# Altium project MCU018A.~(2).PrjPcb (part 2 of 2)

## Sheet MCU018A_Main.SchDoc
size 558 x 431 mm; Date: Not shown in title block; ApprovedBy: Not shown in title block; CheckedBy: Not shown in title block; Author: Not shown in title block; CompanyName: Not shown in title block; Engineer: Eddie LaCost; Organization: Not shown in title block; Address1: Not shown in title block; Address2: Not shown in title block; Address3: Not shown in title block; Address4: Not shown in title block; DocumentNumber: 2; Revision: Use project parameter SCH_Rev; SheetNumber: 2; SheetTotal: 6; PageSetup: Record=PageOptions¦CenterHorizontal=True¦CenterVertical=True¦PrintScale=1.00¦XCorrection=1.00¦YCorrection=1.00¦PrintKind=0¦BorderSize=5000000¦LeftOffset=0¦BottomOffset=0¦Orientation=2¦PaperLength=1000¦PaperWidth=1000¦Scale=100¦PaperSource=15¦PrintQuality=600¦MediaType=1¦DitherType=10¦PaperKind=Letter¦PrintScaleMode=1
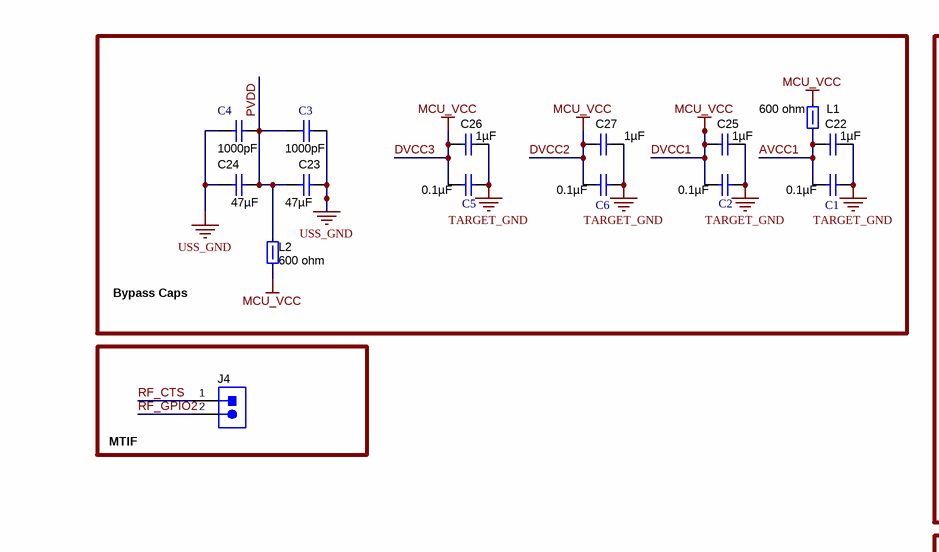
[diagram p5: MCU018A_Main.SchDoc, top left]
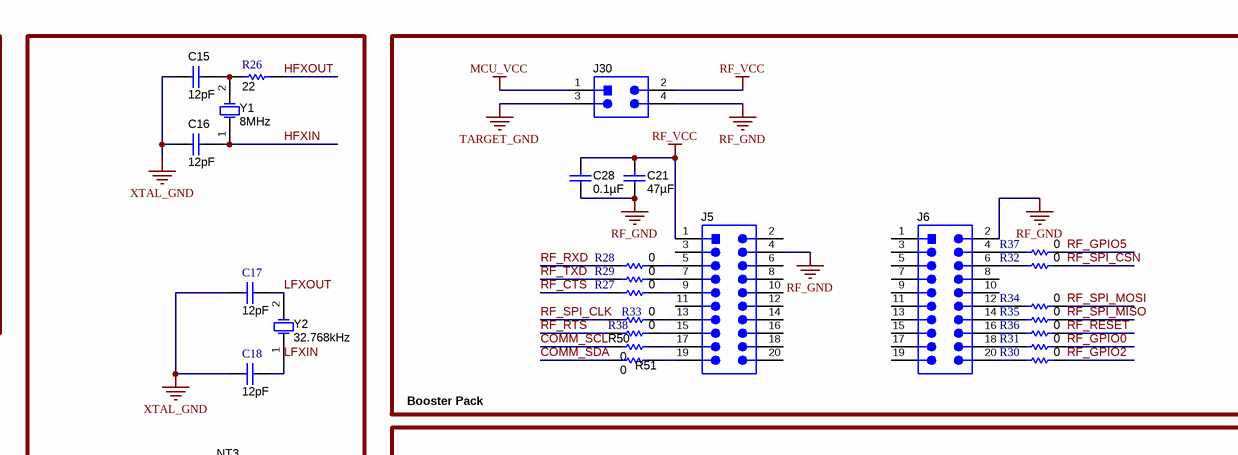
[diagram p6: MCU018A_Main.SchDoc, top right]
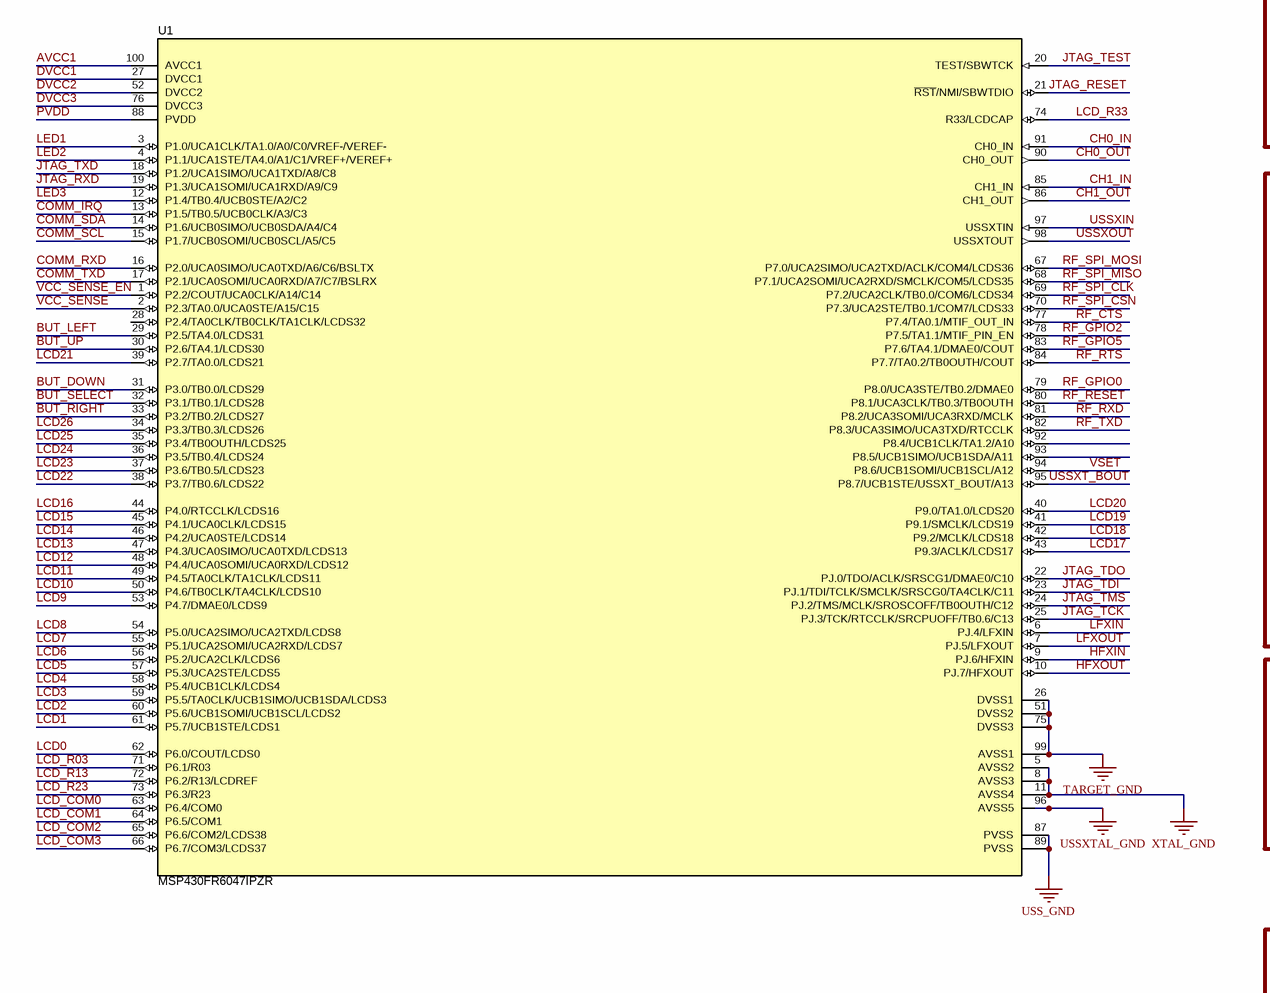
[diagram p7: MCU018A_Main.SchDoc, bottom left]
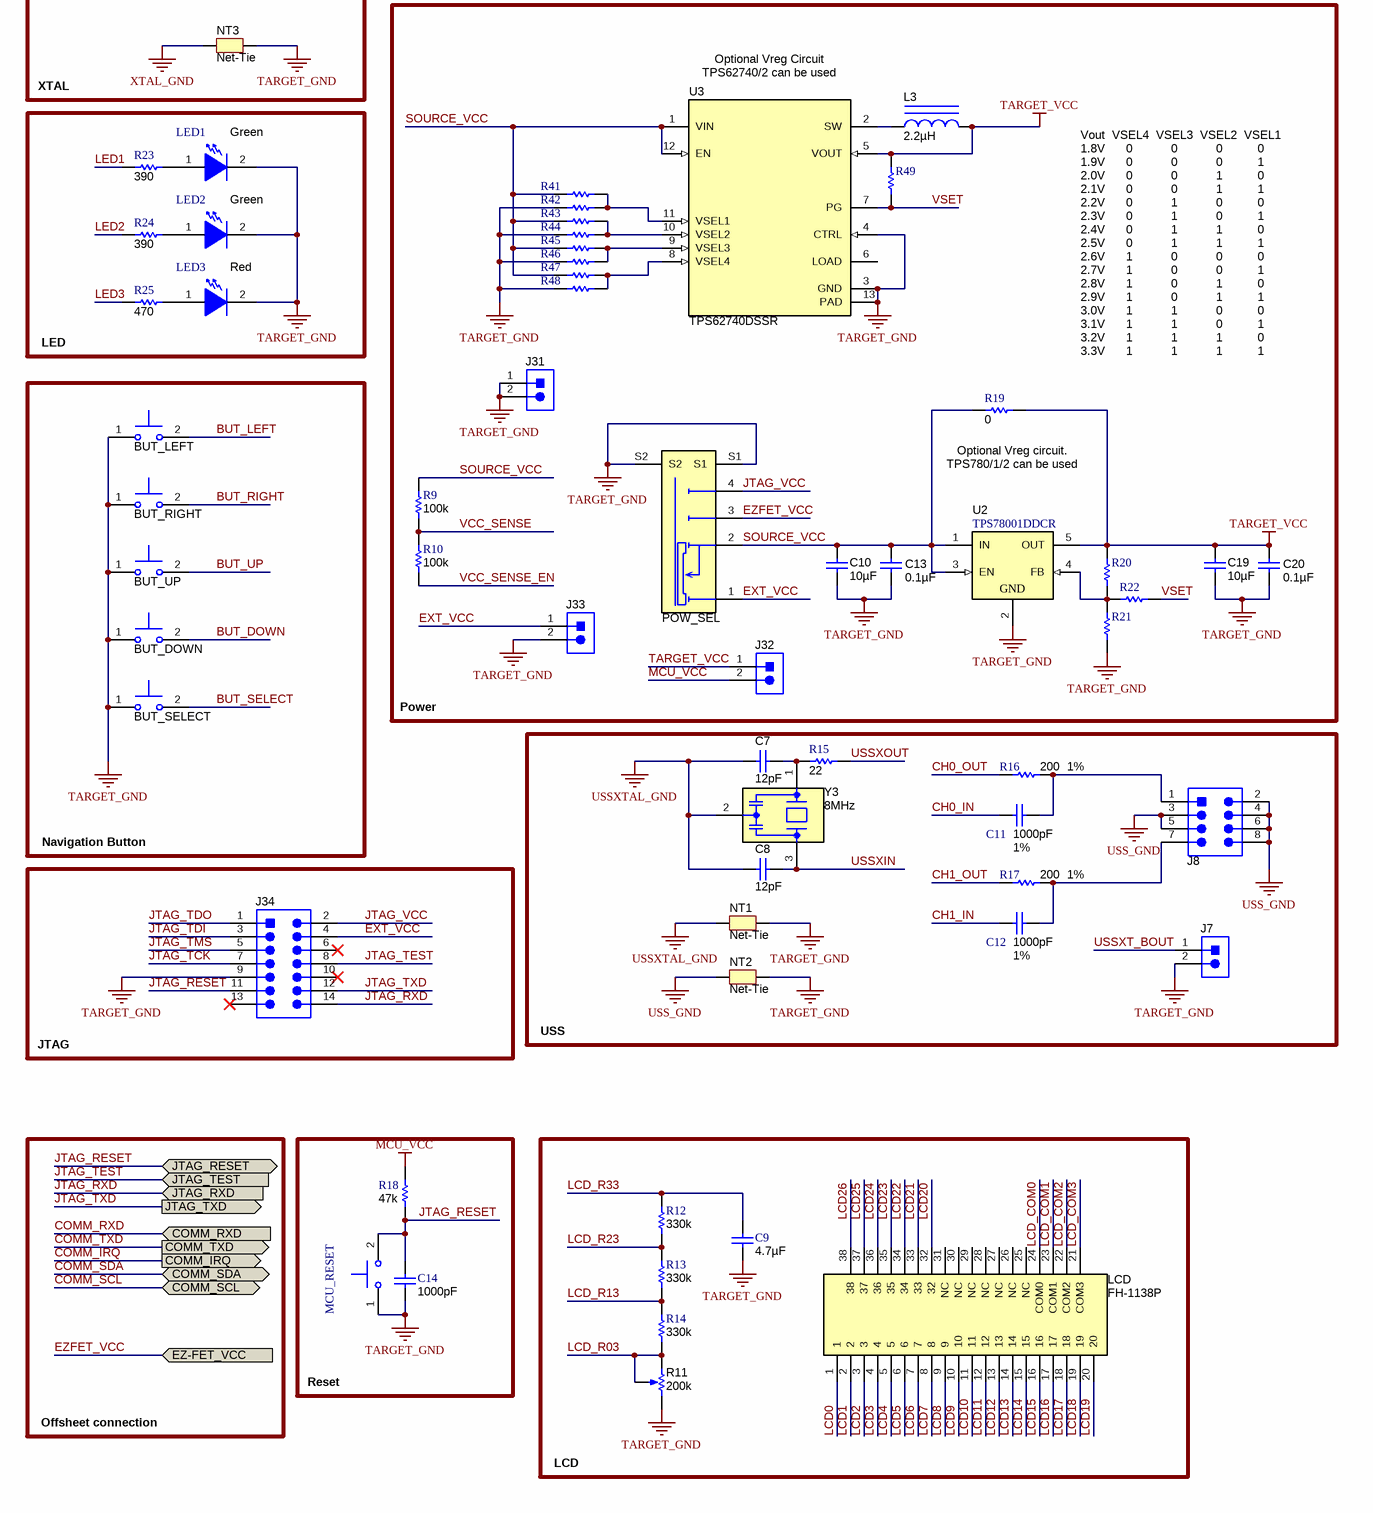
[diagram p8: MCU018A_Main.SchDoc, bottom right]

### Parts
BUT_DOWN  TL1015AF160QG  [SW_TL1015AF160QG]  (value not drawn)
BUT_LEFT  TL1015AF160QG  [SW_TL1015AF160QG]  (value not drawn)
BUT_RIGHT  TL1015AF160QG  [SW_TL1015AF160QG]  (value not drawn)
BUT_SELECT  TL1015AF160QG  [SW_TL1015AF160QG]  (value not drawn)
BUT_UP  TL1015AF160QG  [SW_TL1015AF160QG]  (value not drawn)
C1  ValueDisplayed: 0.1µF  [0402S]  (hidden comment: GRM155R71C104KA88D)
C2  ValueDisplayed: 0.1µF  [0402S]  (hidden comment: GRM155R71C104KA88D)
C3  ValueDisplayed: 1000pF  [0402S]  (hidden comment: GRM1555C1H102JA01D)
C4  ValueDisplayed: 1000pF  [0402S]  (hidden comment: GRM1555C1H102JA01D)
C5  ValueDisplayed: 0.1µF  [0402S]  (hidden comment: GRM155R71C104KA88D)
C6  ValueDisplayed: 0.1µF  [0402S]  (hidden comment: GRM155R71C104KA88D)
C7  ValueDisplayed: 12pF  [0402]  (hidden comment: GRM1555C1H120JA01D)
C8  ValueDisplayed: 12pF  [0402]  (hidden comment: GRM1555C1H120JA01D)
C9  ValueDisplayed: 4.7µF  [0805_HV]  (hidden comment: GRM21BR71C475KA73L)
C10  ValueDisplayed: 10µF  [0603S]  (hidden comment: GRM188R61A106ME69D)
C11  ValueDisplayed: 1000pF  Tolerance_%: 1%  [0603S]  (hidden comment: GRM1885C1H102FA01J)
C12  ValueDisplayed: 1000pF  Tolerance_%: 1%  [0603S]  (hidden comment: GRM1885C1H102FA01J)
C13  ValueDisplayed: 0.1µF  [0402S]  (hidden comment: GRM155R71C104KA88D)
C14  ValueDisplayed: 1000pF  [0402S]  (hidden comment: GRM1555C1H102JA01D)
C15  ValueDisplayed: 12pF  [0402]  (hidden comment: GRM1555C1H120JA01D)
C16  ValueDisplayed: 12pF  [0402]  (hidden comment: GRM1555C1H120JA01D)
C17  ValueDisplayed: 12pF  [0402S]  (hidden comment: GRM1555C1H120JA01D)
C18  ValueDisplayed: 12pF  [0402S]  (hidden comment: GRM1555C1H120JA01D)
C19  ValueDisplayed: 10µF  [0603S]  (hidden comment: GRM188R61A106ME69D)
C20  ValueDisplayed: 0.1µF  [0402S]  (hidden comment: GRM155R71C104KA88D)
C21  ValueDisplayed: 47µF  [0805_HV]  (hidden comment: GRM21BR60J476ME15L)
C22  ValueDisplayed: 1µF  [0603S]  (hidden comment: GRM188R71A105KA61D)
C23  ValueDisplayed: 47µF  [0805L]  (hidden comment: GRM21BR60J476ME15L)
C24  ValueDisplayed: 47µF  [0805L]  (hidden comment: GRM21BR60J476ME15L)
C25  ValueDisplayed: 1µF  [0603S]  (hidden comment: GRM188R71A105KA61D)
C26  ValueDisplayed: 1µF  [0603S]  (hidden comment: GRM188R71A105KA61D)
C27  ValueDisplayed: 1µF  [0603S]  (hidden comment: GRM188R71A105KA61D)
C28  ValueDisplayed: 0.1µF  [0402]  (hidden comment: GRM155R71C104KA88D)
J4  HMTSW-102-07-G-S-240  [SAMTEC_HMTSW-102-07-G-S-240]  (value not drawn)
J5  TSW-110-07-G-D  [TSW-110-07-G-D]  (value not drawn)
J6  TSW-110-07-G-D  [TSW-110-07-G-D]  (value not drawn)
J7  HMTSW-102-07-G-S-240  [SAMTEC_HMTSW-102-07-G-S-240]  (value not drawn)
J8  TSW-104-07-G-D  [TSW-104-07-G-D]  (value not drawn)
J30  TSW-102-07-G-D  [TSW-102-07-G-D]  (value not drawn)
J31  TSW-102-07-G-S  [TSW-102-07-G-S]  (value not drawn)
J32  TSW-102-07-G-S  [TSW-102-07-G-S]  (value not drawn)
J33  TSW-102-07-G-S  [TSW-102-07-G-S]  (value not drawn)
J34  SBH11-PBPC-D07-ST-BK  [CONN_SBH11-PBPC-D07-ST-BK]  (value not drawn)
L1  value 600 ohm  [0805L]  (hidden comment: MPZ2012S601A)
L2  value 600 ohm  [0805L]  (hidden comment: MPZ2012S601A)
L3  ValueDisplayed: 2.2µH  [VLF302515MT]  (hidden comment: VLF302515MT-2R2M)
LCD  FH-1138P  [ADKOM_FH-1138P]
LED1  value Green  [LTST-C191_Green]  (hidden comment: LTST-C191TGKT)
LED2  value Green  [LTST-C191_Green]  (hidden comment: LTST-C191TGKT)
LED3  value Red  [LED_LTST-C190_Red]  (hidden comment: LTST-C190CKT)
MCU_RESET  B3U-1000P  [SW_B3U-1000P]  (value not drawn)
NT1  Net-Tie  [Net-Tie_50milWide_30milLong]  (net tie, no BOM)
NT2  Net-Tie  [Net-Tie_50milWide_30milLong]  (net tie, no BOM)
NT3  Net-Tie  [Net-Tie_50milWide_30milLong]  (net tie, no BOM)
POW_SEL  SS-13D16-VG 4 PA  [SW_SS-13D16-VG]  (value not drawn)
R9  ValueDisplayed: 100k  [0402S]  (hidden comment: CRCW0402100KJNED)
R10  ValueDisplayed: 100k  [0402S]  (hidden comment: CRCW0402100KJNED)
R11  value 200k  [TRIM_3224W]  (hidden comment: 3224W-1-204E)
R12  ValueDisplayed: 330k  [0402S]  (hidden comment: CRCW0402330KJNED)
R13  ValueDisplayed: 330k  [0402S]  (hidden comment: CRCW0402330KJNED)
R14  ValueDisplayed: 330k  [0402S]  (hidden comment: CRCW0402330KJNED)
R15  ValueDisplayed: 22  [0402S]  (hidden comment: CRCW040222R0JNED)
R16  ValueDisplayed: 200  Value1: 1%  [0402S]  (hidden comment: CRCW0402200RFKED)
R17  ValueDisplayed: 200  Value1: 1%  [0402S]  (hidden comment: CRCW0402200RFKED)
R18  ValueDisplayed: 47k  [0402S]  (hidden comment: CRCW040247K0JNED)
R19  ValueDisplayed: 0  [0805_HV]  (hidden comment: CRCW08050000Z0EA)
R20  Used in BOM report  [0402S]  (value not drawn)
R21  Used in BOM report  [0402S]  (value not drawn)
R22  Used in BOM report  [0402S]  (value not drawn)
R23  ValueDisplayed: 390  [0402S]  (hidden comment: CRCW0402390RJNED)
R24  ValueDisplayed: 390  [0402S]  (hidden comment: CRCW0402390RJNED)
R25  ValueDisplayed: 470  [0402S]  (hidden comment: CRCW0402470RJNED)
R26  ValueDisplayed: 22  [0402S]  (hidden comment: CRCW040222R0JNED)
R27  ValueDisplayed: 0  [0402S]  (hidden comment: CRCW04020000Z0ED)
R28  ValueDisplayed: 0  [0402S]  (hidden comment: CRCW04020000Z0ED)
R29  ValueDisplayed: 0  [0402S]  (hidden comment: CRCW04020000Z0ED)
R30  ValueDisplayed: 0  [0402S]  (hidden comment: CRCW04020000Z0ED)
R31  ValueDisplayed: 0  [0402S]  (hidden comment: CRCW04020000Z0ED)
R32  ValueDisplayed: 0  [0402S]  (hidden comment: CRCW04020000Z0ED)
R33  ValueDisplayed: 0  [0402S]  (hidden comment: CRCW04020000Z0ED)
R34  ValueDisplayed: 0  [0402S]  (hidden comment: CRCW04020000Z0ED)
R35  ValueDisplayed: 0  [0402S]  (hidden comment: CRCW04020000Z0ED)
R36  ValueDisplayed: 0  [0402S]  (hidden comment: CRCW04020000Z0ED)
R37  ValueDisplayed: 0  [0402S]  (hidden comment: CRCW04020000Z0ED)
R38  ValueDisplayed: 0  [0402S]  (hidden comment: CRCW04020000Z0ED)
R41  Used in BOM report  [0402S]  (value not drawn)
R42  Used in BOM report  [0402S]  (value not drawn)
R43  Used in BOM report  [0402S]  (value not drawn)
R44  Used in BOM report  [0402S]  (value not drawn)
R45  Used in BOM report  [0402S]  (value not drawn)
R46  Used in BOM report  [0402S]  (value not drawn)
R47  Used in BOM report  [0402S]  (value not drawn)
R48  Used in BOM report  [0402S]  (value not drawn)
R49  Used in BOM report  [0402S]  (value not drawn)
R50  ValueDisplayed: 0  [0402S]  (hidden comment: CRCW04020000Z0ED)
R51  ValueDisplayed: 0  [0402S]  (hidden comment: CRCW04020000Z0ED)
U1  MSP430FR6047IPZR  [PZ0100A_N]
U2  TPS78001DDCR  [DDC0005A_N]
U3  TPS62740DSSR  [DSS0012A]
Y1  Frequency: 8MHz  [Abracon_ABM3]  (hidden comment: ABM3-8.000MHZ-D2Y-T)
Y2  Frequency: 32.768kHz  [XTAL_ABS07]  (hidden comment: ABS07-32.768KHZ-9-T)
Y3  Frequency: 8MHz  [Abracon_AWSCR-CV]  (hidden comment: AWSCR-8.00CV-T)

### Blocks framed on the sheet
Bypass Caps: C1-C6 C22-C27 L1 L2
XTAL: C15-C18 NT3 R26 Y1 Y2
Booster Pack: C21 C28 J5 J6 J30 R27-R38 R50 R51
MTIF: J4
LED: LED1-LED3 R23-R25
Navigation Button: BUT_DOWN BUT_LEFT BUT_RIGHT BUT_SELECT BUT_UP
USS: C7 C8 C11 C12 J7 J8 NT1 NT2 R15-R17 Y3
JTAG: J34
Reset: C14 MCU_RESET R18
LCD: C9 LCD R11-R14

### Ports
COMM_IRQ (out), COMM_RXD (in), COMM_SCL (bidir), COMM_SDA (bidir), COMM_TXD (out), EZ-FET_VCC, JTAG_RESET (bidir), JTAG_RXD (in), JTAG_TEST (in), JTAG_TXD (out)

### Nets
DVCC1: C2.2 C5.1 C6.1 C25.1 C26.1 C27.2 J30.1 J32.2 L1.2 L2.2 R18.2 U1.27(DVCC1) U1.52(DVCC2) U1.76(DVCC3)  [also labelled DVCC2, DVCC3, MCU_VCC]
EZFET_VCC: POW_SEL.3 ; port EZ-FET_VCC
RF_GND: C21.2 C28.2 J5.4 J6.2 J30.4
RF_VCC: C21.1 C28.1 J5.1 J30.2
TARGET_GND: BUT_DOWN.1 BUT_LEFT.1 BUT_RIGHT.1 BUT_SELECT.1 BUT_UP.1 C1.2 C2.1 C5.2 C6.2 C9.2 C10.2 C13.2 C14.2 C19.2 C20.2 C22.2 C25.2 C26.2 C27.1 J7.2 J30.3 J31.1 J31.2 J33.2 J34.9 LED1.2(K) LED2.2(K) LED3.2(K) MCU_RESET.1 NT1.2 NT2.2 NT3.2 POW_SEL.S1 POW_SEL.S2 R11.3(CW) R21.1 R42.2 R44.2 R46.2 R48.2 U1.26(DVSS1) U1.51(DVSS2) U1.75(DVSS3) U1.99(AVSS1) U2.2(GND) U3.3(GND) U3.4(CTRL) U3.13(PAD)
TARGET_VCC: C19.1 C20.1 J32.1 L3.2 R19.1 R20.2 R49.1 U2.5(OUT) U3.5(VOUT)
USS_GND: C3.1 C4.2 C23.2 C24.1 J8.2 J8.3 J8.4 J8.5 J8.6 J8.8 NT2.1 U1.87(PVSS) U1.89(PVSS)
USSXTAL_GND: C7.2 C8.2 NT1.1 U1.96(AVSS5) Y3.2(GND)
XTAL_GND: C15.2 C16.2 C17.1 C18.2 NT3.1 U1.5(AVSS2) U1.8(AVSS3) U1.11(AVSS4)
AVCC1: C1.1 C22.1 L1.1 U1.100(AVCC1)
BUT_DOWN: BUT_DOWN.2 U1.31(P3.0/TB0.0/LCDS29)
BUT_LEFT: BUT_LEFT.2 U1.29(P2.5/TA4.0/LCDS31)
BUT_RIGHT: BUT_RIGHT.2 U1.33(P3.2/TB0.2/LCDS27)
BUT_SELECT: BUT_SELECT.2 U1.32(P3.1/TB0.1/LCDS28)
BUT_UP: BUT_UP.2 U1.30(P2.6/TA4.1/LCDS30)
CH0_IN: C11.1 U1.91(CH0_IN)
CH0_OUT: R16.2 U1.90(CH0_OUT)
CH1_IN: C12.1 U1.85(CH1_IN)
CH1_OUT: R17.2 U1.86(CH1_OUT)
COMM_IRQ: U1.13(P1.5/TB0.5/UCB0CLK/A3/C3) ; port COMM_IRQ
COMM_RXD: U1.16(P2.0/UCA0SIMO/UCA0TXD/A6/C6/BSLTX) ; port COMM_RXD
COMM_SCL: R50.1 U1.15(P1.7/UCB0SOMI/UCB0SCL/A5/C5) ; port COMM_SCL
COMM_SDA: R51.1 U1.14(P1.6/UCB0SIMO/UCB0SDA/A4/C4) ; port COMM_SDA
COMM_TXD: U1.17(P2.1/UCA0SOMI/UCA0RXD/A7/C7/BSLRX) ; port COMM_TXD
EXT_VCC: J33.1 J34.4 POW_SEL.1
HFXIN: C16.1 U1.9(PJ.6/HFXIN) Y1.1(OSC1)
HFXOUT: R26.2 U1.10(PJ.7/HFXOUT)
JTAG_RESET: C14.1 J34.11 MCU_RESET.2 R18.1 U1.21(~{RST}/NMI/SBWTDIO) ; port JTAG_RESET
JTAG_RXD: J34.14 U1.19(P1.3/UCA1SOMI/UCA1RXD/A9/C9) ; port JTAG_RXD
JTAG_TCK: J34.7 U1.25(PJ.3/TCK/RTCCLK/SRCPUOFF/TB0.6/C13)
JTAG_TDI: J34.3 U1.23(PJ.1/TDI/TCLK/SMCLK/SRSCG0/TA4CLK/C11)
JTAG_TDO: J34.1 U1.22(PJ.0/TDO/ACLK/SRSCG1/DMAE0/C10)
JTAG_TEST: J34.8 U1.20(TEST/SBWTCK) ; port JTAG_TEST
JTAG_TMS: J34.5 U1.24(PJ.2/TMS/MCLK/SROSCOFF/TB0OUTH/C12)
JTAG_TXD: J34.12 U1.18(P1.2/UCA1SIMO/UCA1TXD/A8/C8) ; port JTAG_TXD
JTAG_VCC: J34.2 POW_SEL.4
LCD0: LCD.1 U1.62(P6.0/COUT/LCDS0)
LCD1: LCD.2 U1.61(P5.7/UCB1STE/LCDS1)
LCD2: LCD.3 U1.60(P5.6/UCB1SOMI/UCB1SCL/LCDS2)
LCD3: LCD.4 U1.59(P5.5/TA0CLK/UCB1SIMO/UCB1SDA/LCDS3)
LCD4: LCD.5 U1.58(P5.4/UCB1CLK/LCDS4)
LCD5: LCD.6 U1.57(P5.3/UCA2STE/LCDS5)
LCD6: LCD.7 U1.56(P5.2/UCA2CLK/LCDS6)
LCD7: LCD.8 U1.55(P5.1/UCA2SOMI/UCA2RXD/LCDS7)
LCD8: LCD.9 U1.54(P5.0/UCA2SIMO/UCA2TXD/LCDS8)
LCD9: LCD.10 U1.53(P4.7/DMAE0/LCDS9)
LCD10: LCD.11 U1.50(P4.6/TB0CLK/TA4CLK/LCDS10)
LCD11: LCD.12 U1.49(P4.5/TA0CLK/TA1CLK/LCDS11)
LCD12: LCD.13 U1.48(P4.4/UCA0SOMI/UCA0RXD/LCDS12)
LCD13: LCD.14 U1.47(P4.3/UCA0SIMO/UCA0TXD/LCDS13)
LCD14: LCD.15 U1.46(P4.2/UCA0STE/LCDS14)
LCD15: LCD.16 U1.45(P4.1/UCA0CLK/LCDS15)
LCD16: LCD.17 U1.44(P4.0/RTCCLK/LCDS16)
LCD17: LCD.18 U1.43(P9.3/ACLK/LCDS17)
LCD18: LCD.19 U1.42(P9.2/MCLK/LCDS18)
LCD19: LCD.20 U1.41(P9.1/SMCLK/LCDS19)
LCD20: LCD.32 U1.40(P9.0/TA1.0/LCDS20)
LCD21: LCD.33 U1.39(P2.7/TA0.0/LCDS21)
LCD22: LCD.34 U1.38(P3.7/TB0.6/LCDS22)
LCD23: LCD.35 U1.37(P3.6/TB0.5/LCDS23)
LCD24: LCD.36 U1.36(P3.5/TB0.4/LCDS24)
LCD25: LCD.37 U1.35(P3.4/TB0OUTH/LCDS25)
LCD26: LCD.38 U1.34(P3.3/TB0.3/LCDS26)
LCD_COM0: LCD.24(COM0) U1.63(P6.4/COM0)
LCD_COM1: LCD.23(COM1) U1.64(P6.5/COM1)
LCD_COM2: LCD.22(COM2) U1.65(P6.6/COM2/LCDS38)
LCD_COM3: LCD.21(COM3) U1.66(P6.7/COM3/LCDS37)
LCD_R03: R11.1(CCW) R11.2(WIPER) R14.2 U1.71(P6.1/R03)
LCD_R13: R13.1 R14.1 U1.72(P6.2/R13/LCDREF)
LCD_R23: R12.1 R13.2 U1.73(P6.3/R23)
LCD_R33: C9.1 R12.2 U1.74(R33/LCDCAP)
LED1: R23.1 U1.3(P1.0/UCA1CLK/TA1.0/A0/C0/VREF-/VEREF-)
LED2: R24.1 U1.4(P1.1/UCA1STE/TA4.0/A1/C1/VREF+/VEREF+)
LED3: R25.1 U1.12(P1.4/TB0.4/UCB0STE/A2/C2)
LFXIN: C18.1 U1.6(PJ.4/LFXIN) Y2.1(OSC1)
LFXOUT: C17.2 U1.7(PJ.5/LFXOUT) Y2.2(OSC2)
PVDD: C3.2 C4.1 C23.1 C24.2 L2.1 U1.88(PVDD)
RF_CTS: J4.1 R27.2 U1.77(P7.4/TA0.1/MTIF_OUT_IN)
RF_GPIO0: R31.2 U1.79(P8.0/UCA3STE/TB0.2/DMAE0)
RF_GPIO2: J4.2 R30.2 U1.78(P7.5/TA1.1/MTIF_PIN_EN)
RF_GPIO5: R37.1 U1.83(P7.6/TA4.1/DMAE0/COUT)
RF_RESET: R36.1 U1.80(P8.1/UCA3CLK/TB0.3/TB0OUTH)
RF_RTS: R38.1 U1.84(P7.7/TA0.2/TB0OUTH/COUT)
RF_RXD: R28.2 U1.81(P8.2/UCA3SOMI/UCA3RXD/MCLK)
RF_SPI_CLK: R33.1 U1.69(P7.2/UCA2CLK/TB0.0/COM6/LCDS34)
RF_SPI_CSN: R32.2 U1.70(P7.3/UCA2STE/TB0.1/COM7/LCDS33)
RF_SPI_MISO: R35.2 U1.68(P7.1/UCA2SOMI/UCA2RXD/SMCLK/COM5/LCDS35)
RF_SPI_MOSI: R34.2 U1.67(P7.0/UCA2SIMO/UCA2TXD/ACLK/COM4/LCDS36)
RF_TXD: R29.2 U1.82(P8.3/UCA3SIMO/UCA3TXD/RTCCLK)
SOURCE_VCC: C10.1 C13.1 POW_SEL.2 R9.2 R19.2 R41.2 R43.2 R45.2 R47.2 U2.1(IN) U2.3(EN) U3.1(VIN) U3.12(EN)
USSXIN: C8.1 U1.97(USSXTIN) Y3.3(Out)
USSXOUT: R15.2 U1.98(USSXTOUT)
USSXT_BOUT: J7.1 U1.95(P8.7/UCB1STE/USSXT_BOUT/A13)
VCC_SENSE: R9.1 R10.2 U1.2(P2.3/TA0.0/UCA0STE/A15/C15)
VCC_SENSE_EN: R10.1 U1.1(P2.2/COUT/UCA0CLK/A14/C14)
VSET: R22.1 R49.2 U1.94(P8.6/UCB1SOMI/UCB1SCL/A12) U3.7(PG)
NetC7_1: C7.1 R15.1 Y3.1(In)
NetC11_2: C11.2 J8.1 R16.1
NetC12_2: C12.2 J8.7 R17.1
NetC15_1: C15.1 R26.1 Y1.2(OSC2)
NetJ5_5: J5.5 R28.1
NetJ5_7: J5.7 R29.1
NetJ5_9: J5.9 R27.1
NetJ5_13: J5.13 R33.2
NetJ5_15: J5.15 R38.2
NetJ5_17: J5.17 R50.2
NetJ5_19: J5.19 R51.2
NetJ6_4: J6.4 R37.2
NetJ6_6: J6.6 R32.1
NetJ6_12: J6.12 R34.1
NetJ6_14: J6.14 R35.1
NetJ6_16: J6.16 R36.2
NetJ6_18: J6.18 R31.1
NetJ6_20: J6.20 R30.1
NetL3_1: L3.1 U3.2(SW)
NetLED1_1: LED1.1(A) R23.2
NetLED2_1: LED2.1(A) R24.2
NetLED3_1: LED3.1(A) R25.2
NetR20_1: R20.1 R21.2 R22.2 U2.4(FB)
NetR41_1: R41.1 R42.1 U3.11(VSEL1)
NetR43_1: R43.1 R44.1 U3.10(VSEL2)
NetR45_1: R45.1 R46.1 U3.9(VSEL3)
NetR47_1: R47.1 R48.1 U3.8(VSEL4)

Not connected (* = marked no-connect by the designer): J5 2 3 6 8 10 11 12 14 16 18 20; J6 1 3 5 7 8 9 10 11 13 15 17 19; J34 6* 10* 13*; LCD 25(NC) 26(NC) 27(NC) 28(NC) 29(NC) 30(NC) 31(NC); U1 28(P2.4/TA0CLK/TB0CLK/TA1CLK/LCDS32) 92(P8.4/UCB1CLK/TA1.2/A10) 93(P8.5/UCB1SIMO/UCB1SDA/A11); U3 6(LOAD)

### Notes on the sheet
- Optional Vreg Circuit
- (near U3) TPS62740/2 can be used
- Vout  VSEL4  VSEL3  VSEL2  VSEL1
  1.8V      0           0           0          0
  1.9V      0           0           0          1
  2.0V      0           0           1          0
  2.1V      0           0           1          1
  2.2V      0           1           0          0
  2.3V      0           1           0          1
  2.4V      0           1           1          0
  2.5V      0           1           1          1
  2.6V      1           0           0          0
  2.7V      1           0           0          1
  2.8V      1           0           1          0
  2.9V      1           0           1          1
  3.0V      1           1           0          0
  3.1V      1           1           0          1
  3.2V      1           1           1          0
  3.3V      1           1           1          1
- (near R19) Optional Vreg circuit.
- TPS780/1/2 can be used
- Power
- Offsheet connection

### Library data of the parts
BUT_DOWN BUT_LEFT BUT_RIGHT BUT_SELECT BUT_UP = TL1015AF160QG: Switch, Tactile, SPST-NO, 0.05A, 12V, SMT; Manufacturer: E-Switch; SymbolCreator: a0412235; VDC_V: 12; SwitchFunction: Off-Mom; PositionCount: 1; CurrentRating_mA: 50
C1 C2 C5 C6 = GRM155R71C104KA88D: CAP, CERM, 0.1 µF, 16 V, +/- 10%, X7R, 0402; Manufacturer: MuRata; Value: 0.1uF; Polarized: N; CompType: Capacitor; U/M: EA; Cap_F: 0.0000001; Tolerance_%: 10; Value1: Unknown; VDC_V: 16; Value2: 16V; TaMin_C: -55; TaMax_C: 125; Cap_Case: 0402; AEC Category: Q200
C3 C4 C14 = GRM1555C1H102JA01D: CAP, CERM, 1000 pF, 50 V, +/- 5%, C0G/NP0, 0402; Manufacturer: MuRata; Value: 1000pF; Polarized: N; CompType: Capacitor; U/M: EA; Cap_F: 0.000000001; Tolerance_%: 5; Value1: Unknown; VDC_V: 50; Value2: 50V; TaMin_C: -55; TaMax_C: 125; Cap_Case: 0402; AEC Category: Q200
C7 C8 C15 C16 = GRM1555C1H120JA01D: CAP, CERM, 12 pF, 50 V, +/- 5%, C0G/NP0, 0402; Manufacturer: MuRata; Polarized: N; CompType: Capacitor; Value: 12pF; U/M: EA; Cap_F: 0.000000000012; Tolerance_%: 5; Value1: Unknown; VDC_V: 50; Value2: 50V; TaMin_C: -55; TaMax_C: 125; SizeArea_mm2: 0.5; SizeAreaWB_mm2: 3; SizeX_mm: 1; SizeZ_mm: 0.6; AEC Category: Q200
C9 = GRM21BR71C475KA73L: CAP, CERM, 4.7 µF, 16 V, +/- 10%, X7R, 0805; Manufacturer: MuRata; Value: 4.7uF; Polarized: N; CompType: Capacitor; U/M: EA; Cap_F: 0.0000047; Tolerance_%: 10; ESR_ohm: 0.006; Value1: 0.006 ohm; VDC_V: 16; Value2: 16V; TaMin_C: -55; TaMax_C: 125; Cap_Case: 0805; AEC Category: Q200
C10 C19 = GRM188R61A106ME69D: CAP, CERM, 10 µF, 10 V, +/- 20%, X5R, 0603; Manufacturer: MuRata; Polarized: N; CompType: Capacitor; Value: 10uF; U/M: EA; Cap_F: 0.00001; Tolerance_%: 20; Value1: Unknown; VDC_V: 10; Value2: 10V; TaMin_C: -55; TaMax_C: 85; Cap_Case: 0603; AEC Category: Q200; SizeArea_mm2: 1.28; SizeAreaWB_mm2: 4.68; SizeX_mm: 1.6; SizeY_mm: 0.8; SizeZ_mm: 1
C11 C12 = GRM1885C1H102FA01J: CAP, CERM, 1000 pF, 50 V, +/- 1%, C0G/NP0, 0603; Manufacturer: MuRata; Value: 1000pF; Polarized: N; CompType: Capacitor; U/M: EA; Cap_F: 0.000000001; Value1: Unknown; VDC_V: 50; Value2: 50V; TaMin_C: -55; TaMax_C: 125; Cap_Case: 0603; AEC Category: Q200
C13 C20 = GRM155R71C104KA88D: CAP, CERM, 0.1 µF, 16 V, +/- 10%, X7R, 0402; Manufacturer: MuRata; Polarized: N; CompType: Capacitor; Value: 0.1uF; U/M: EA; Cap_F: 0.0000001; Tolerance_%: 10; Value1: Unknown; VDC_V: 16; Value2: 16V; TaMin_C: -55; TaMax_C: 125; Cap_Case: 0402; AEC Category: Q200
C17 C18 = GRM1555C1H120JA01D: CAP, CERM, 12 pF, 50 V, +/- 5%, C0G/NP0, 0402; Manufacturer: MuRata; Value: 12pF; Polarized: N; CompType: Capacitor; U/M: EA; Cap_F: 0.000000000012; Tolerance_%: 5; Value1: Unknown; VDC_V: 50; Value2: 50V; TaMin_C: -55; TaMax_C: 125; Cap_Case: 0402; AEC Category: Q200
C21 = GRM21BR60J476ME15L: CAP, CERM, 47 µF, 6.3 V, +/- 20%, X5R, 0805; Manufacturer: MuRata; Polarized: N; CompType: Capacitor; Value: 47uF; U/M: EA; Cap_F: 0.000047; Tolerance_%: 20; Value1: Unknown; VDC_V: 6.3; Value2: 6.3V; TaMin_C: -55; TaMax_C: 85; Cap_Case: 0805; SizeArea_mm2: 2.5; SizeAreaWB_mm2: 6.75; SizeX_mm: 2; SizeY_mm: 1.25; SizeZ_mm: 1.45; AEC Category: Q200
C22 = GRM188R71A105KA61D: CAP, CERM, 1 µF, 10 V, +/- 10%, X7R, 0603; Manufacturer: MuRata; Polarized: N; CompType: Capacitor; Value: 1uF; U/M: EA; Cap_F: 0.000001; Tolerance_%: 10; ESR_ohm: 0.011; Value1: 0.011 ohm; Value2: 10V; TaMin_C: -55; TaMax_C: 125; Cap_Case: 0603; AEC Category: Q200; SizeArea_mm2: 1.28; SizeAreaWB_mm2: 4.68; SizeX_mm: 1.6; SizeY_mm: 0.8; SizeZ_mm: 1
C23 C24 = GRM21BR60J476ME15L: CAP, CERM, 47 µF, 6.3 V, +/- 20%, X5R, 0805; Manufacturer: MuRata; Polarized: N; CompType: Capacitor; Value: 47uF; U/M: EA; Cap_F: 0.000047; Tolerance_%: 20; Value1: Unknown; VDC_V: 6.3; Value2: 6.3V; TaMin_C: -55; TaMax_C: 85; Cap_Case: 0805; AEC Category: Q200; SizeArea_mm2: 2.5; SizeAreaWB_mm2: 6.75; SizeX_mm: 2; SizeY_mm: 1.25; SizeZ_mm: 1.45
C25-C27 = GRM188R71A105KA61D: CAP, CERM, 1 µF, 10 V, +/- 10%, X7R, 0603; Manufacturer: MuRata; Polarized: N; CompType: Capacitor; Value: 1uF; U/M: EA; Cap_F: 0.000001; Tolerance_%: 10; ESR_ohm: 0.011; Value1: 0.011 ohm; Value2: 10V; TaMin_C: -55; TaMax_C: 125; Cap_Case: 0603; SizeArea_mm2: 1.28; SizeAreaWB_mm2: 4.68; SizeX_mm: 1.6; SizeY_mm: 0.8; SizeZ_mm: 1; AEC Category: Q200
C28 = GRM155R71C104KA88D: CAP, CERM, 0.1 µF, 16 V, +/- 10%, X7R, 0402; Manufacturer: MuRata; Polarized: N; CompType: Capacitor; Value: 0.1uF; U/M: EA; Cap_F: 0.0000001; Tolerance_%: 10; Value1: Unknown; VDC_V: 16; Value2: 16V; TaMin_C: -55; TaMax_C: 125; SizeArea_mm2: 0.5; SizeAreaWB_mm2: 3; SizeX_mm: 1; SizeZ_mm: 0.6; AEC Category: Q200
J4 J7 = HMTSW-102-07-G-S-240: Header, 100mil, 2x1, Gold, TH; Manufacturer: Samtec; SymbolCreator: a0412235
J5 J6 = TSW-110-07-G-D: Header, 100mil, 10x2, Gold, TH; Manufacturer: Samtec; SymbolCreator: a0412235; Pitch_mm: 2.54; Gender: Male; Shrouded: N; Row_Count: 2; Current_A: 6.3; Voltage_V: 550; Cert_CSA: Y
J8 = TSW-104-07-G-D: Header, 100mil, 4x2, Gold, TH; Manufacturer: Samtec; SymbolCreator: a0411947; Pitch_mm: 2.54; Gender: Male; Shrouded: N; Row_Count: 2; Current_A: 6.3; Voltage_V: 550; Cert_CSA: Y
J30 = TSW-102-07-G-D: Header, 100mil, 2x2, Gold, TH; Manufacturer: Samtec; SymbolCreator: a0412235; Pitch_mm: 2.54; Gender: Male; Shrouded: N; Row_Count: 2; Current_A: 6.3; Voltage_V: 550; Cert_CSA: Y
J31-J33 = TSW-102-07-G-S: Header, 100mil, 2x1, Gold, TH; Manufacturer: Samtec; SymbolCreator: a0412235; Pitch_mm: 2.54; Gender: Male; Shrouded: N; Row_Count: 1; Current_A: 6.3; Voltage_V: 550; Cert_CSA: Y
J34 = SBH11-PBPC-D07-ST-BK: Header (shrouded), 100 mil, 7x2, Gold, TH; Manufacturer: Sullins Connector Solutions; SymbolCreator: a0412235
L1 L2 = MPZ2012S601A: Ferrite Bead, 600 ohm @ 100 MHz, 2 A, 0805; Manufacturer: TDK; Alternate PartNumber: MPZ2012S601AT000; Imax_A: 2; DCR_ohm: 0.1; Value1: 0.1 ohm; Value2: 2A; ZTyp@100MHz_Ohm: 600
L3 = VLF302515MT-2R2M: Inductor, Shielded, Ferrite, 2.2 µH, 1.57 A, 0.042 ohm, SMD; Manufacturer: TDK; Value: 2.2uH; Ind_H: 2.2E-6; Imax_A: 1.57; Irms: 2.71A @ 40C rise; Isat: 1.57A @ 30% inductance drop; DCR_ohm: 0.042; Value2: 1.57A; AEC Category: Q200
LCD = FH-1138P: 108 Segment LCD Display, TH; Manufacturer: Adkom Elektronik; SymbolCreator: Altium; SizeAreaWB_mm2: 1571.8; SizeArea_mm2: 1405.6; SizeX_mm: 25.1; SizeY_mm: 56; SizeZ_mm: 3.1
LED1 LED2 = LTST-C191TGKT: LED, Green, SMD; Manufacturer: Lite-On; Type: InGaN; Vf_V: 3.2; Value2: 3.2V; Io_A: 0.02; Value1: W; U/M: EA
LED3 = LTST-C190CKT: LED, Red, SMD; Manufacturer: Lite-On; Vf_V: 2; Value2: 2V; Io_A: 0.02; Tjmax_C: 85; Power_TotalModule: 0.0625; Value1: 0.0625W; U/M: EA
MCU_RESET = B3U-1000P: SWITCH TACTILE SPST-NO 0.05A 12V; Manufacturer: Omron Electronic Components; SymbolCreator: a0412235; VDC_V: 12; SwitchFunction: Off-Mom; PositionCount: 1; CurrentRating_mA: 50
NT1-NT3 = Net-Tie: Single point connection between nets.; SymbolCreator: codlsc
POW_SEL = SS-13D16-VG 4 PA: Switch, Slide, SP3T, On-On-On, 3 Pos, 0.3A, 30 VDC, TH; Manufacturer: C&K Components; SymbolCreator: Altium; VDC_V: 30; PositionCount: 3; CurrentRating_mA: 300
R9 R10 = CRCW0402100KJNED: RES, 100 k, 5%, 0.063 W, 0402; Manufacturer: Vishay-Dale; Value: 100k; CompType: Resistor; Res_ohm: 100000; Tolerance_%: 5; Power_W: 0.063; Value2: 0.063W; VDC_V: 50; TempCo: 200 ppm/C; EIA_Code: E24; U/M: EA
R11 = 3224W-1-204E: Trimmer, 200 K, 0.25 W, SMD; Manufacturer: Bourns; Sim Note: Enter the Resistance value and the set point into parameter fields.; SymbolCreator: a0412235
R12-R14 = CRCW0402330KJNED: RES, 330 k, 5%, 0.063 W, 0402; Manufacturer: Vishay-Dale; Value: 330k; CompType: Resistor; Res_ohm: 330000; Tolerance_%: 5; Power_W: 0.063; Value2: 0.063W; VDC_V: 50; TempCo: 200 ppm/C; EIA_Code: E24; U/M: EA; AEC Category: Q200
R15 R26 = CRCW040222R0JNED: RES, 22, 5%, 0.063 W, 0402; Manufacturer: Vishay-Dale; Value: 22; CompType: Resistor; Value_Code: 22R0; Tolerance_%: 5; Power_W: 0.063; Value2: 0.063W; VDC_V: 50; TempCo: 200 ppm/C; EIA_Code: E24; U/M: EA; AEC Category: Q200
R16 R17 = CRCW0402200RFKED: RES, 200, 1%, 0.063 W, 0402; Manufacturer: Vishay-Dale; Value: 200; CompType: Resistor; Value_Code: 200R; Tolerance_%: 1; Power_W: 0.063; Value2: 0.063W; VDC_V: 50; TempCo: 100 ppm/C; EIA_Code: E96; U/M: EA; AEC Category: Q200
R18 = CRCW040247K0JNED: RES, 47 k, 5%, 0.063 W, 0402; Manufacturer: Vishay-Dale; Value: 47k; CompType: Resistor; Res_ohm: 47000; Value_Code: 47k0; Tolerance_%: 5; Power_W: 0.063; Value2: 0.063W; VDC_V: 50; TempCo: 200 ppm/C; EIA_Code: E24; U/M: EA
R19 = CRCW08050000Z0EA: RES, 0, 5%, 0.125 W, 0805; Manufacturer: Vishay-Dale; Value: 0; CompType: Resistor; Value_Code: 0000; Tolerance_%: 5; Power_W: 0.125; Value2: 0.125W; VDC_V: 150; TempCo: 200 ppm/C; EIA_Code: E24; U/M: EA; AEC Category: Q200
R20-R22 R41-R49 = Resistor: RES, xxx ohm, x%, xW, [PackageReference]; U/M: EA
R23 R24 = CRCW0402390RJNED: RES, 390, 5%, 0.063 W, 0402; Manufacturer: Vishay-Dale; Value: 390; CompType: Resistor; Value_Code: 390R; Tolerance_%: 5; Power_W: 0.063; Value2: 0.063W; VDC_V: 50; TempCo: 200 ppm/C; EIA_Code: E24; U/M: EA; AEC Category: Q200
R25 = CRCW0402470RJNED: RES, 470, 5%, 0.063 W, 0402; Manufacturer: Vishay-Dale; Value: 470; CompType: Resistor; Value_Code: 470R; Tolerance_%: 5; Power_W: 0.063; Value2: 0.063W; VDC_V: 50; TempCo: 200 ppm/C; EIA_Code: E24; U/M: EA; AEC Category: Q200
R27-R38 = CRCW04020000Z0ED: RES, 0, 5%, 0.063 W, 0402; Manufacturer: Vishay-Dale; Value: 0; CompType: Resistor; Value_Code: 0000; Tolerance_%: 5; Power_W: 0.063; Value2: 0.063W; VDC_V: 50; TempCo: 200 ppm/C; EIA_Code: E24; U/M: EA
R50 R51 = CRCW04020000Z0ED: RES, 0, 5%, 0.063 W, 0402; Manufacturer: Vishay-Dale; CompType: Resistor; Value: 0; Value_Code: 0000; Tolerance_%: 5; Power_W: 0.063; Value2: 0.063W; VDC_V: 50; TempCo: 200 ppm/C; SizeArea_mm2: 0.5; SizeX_mm: 1; SizeZ_mm: 0.6; EIA_Code: E24; U/M: EA; AEC Category: Q200
U1 = MSP430FR6047IPZR: Mixed-Signal Microcontroller, PZ0100A (LQFP-100); Manufacturer: Texas Instruments; SymbolCreator: Altium; SizeArea_mm2: 256; SizeAreaWB_mm2: 324; SizeX_mm: 16; SizeZ_mm: 1.6; CompType: IC; U/M: EA
U2 = TPS78001DDCR: Single Output LDO, 150 mA, Adjustable 1.22 to 5.25 V Output, 2.2 to 5.5 V Input, with 500 nA Quiescent Current, 5-pin SOT (DDC), -40 to 125 degC, Green (RoHS & no Sb/Br); Manufacturer: Texas Instruments; Alternate PartNumber: Equivalent; Accuracy(%): 3; Dynamic Voltage Scaling: TRUE; Iout(Max)(A): 0.15; Iq(Typ)(mA): 0.0005; SubFamily: Single Channel LDO; Vdo(Typ)(mV): 200; Vin(Max)(V): 5.5; Vin(Min)(V): 2.2; Vout Adj(Max)(V): 5.25; Vout Adj(Min)(V): 1.22
U3 = TPS62740DSSR: 360nA IQ Step Down Converter for Low Power Applications, DSS0012A; Alternate PartNumber: TPS62740DSST; Manufacturer: Texas Instruments; SymbolCreator: Altium; SizeArea_mm2: 6; SizeAreaWB_mm2: 12; SizeX_mm: 3; SizeY_mm: 2; SizeZ_mm: 0.8; CompType: IC; U/M: EA
Y1 = ABM3-8.000MHZ-D2Y-T: Crystal, 8MHz, SMD; Manufacturer: Abracon Corporation; SymbolCreator: a0412235; U/M: EA; TaMin_C: -40; TaMax_C: 85; Frequency Stability: ±30ppm
Y2 = ABS07-32.768KHZ-9-T: CRYSTAL, 32.768KHZ, 9PF, SMD; Manufacturer: Abracon Corporation; SymbolCreator: a0412235; U/M: EA; TaMin_C: -40; TaMax_C: 85; Frequency Stability: ±20ppm
Y3 = AWSCR-8.00CV-T: Ceramic Resonator, 8MHz, 22pF, SMD; Manufacturer: Abracon Corporation; SymbolCreator: a0799721; SizeAreaWB_mm2: 19.27; SizeArea_mm2: 11.47; SizeX_mm: 3.7; SizeY_mm: 3.1; SizeZ_mm: 1.2; U/M: EA; TaMin_C: -25; TaMax_C: 85

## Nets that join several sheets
EZFET_VCC: MCU018A_Block (J2.2), MCU018A_Main (POW_SEL.3)
TARGET_GND: MCU018A_Block (J2.4), MCU018A_Main (48 pins)
USB_GND: MCU018A_Block (J2.3 RUSB.1 USB.5), MCU018A_USB Hub and Pow (31 pins), MCU018A_Comm Interface (28 pins), MCU018A_ezFET_lite (46 pins)
USB_LDO: MCU018A_Block (J10.3), MCU018A_USB Hub and Pow (12 pins), MCU018A_Comm Interface (12 pins), MCU018A_ezFET_lite (16 pins)
USB_VBUS: MCU018A_Block (USB.1), MCU018A_USB Hub and Pow (6 pins), MCU018A_Comm Interface (U200.53), MCU018A_ezFET_lite (9 pins)
COMM_IRQ: MCU018A_Block (J1.1), MCU018A_Main (U1.13)
COMM_RXD: MCU018A_Block (J1.7), MCU018A_Main (U1.16)
COMM_SCL: MCU018A_Block (J1.5), MCU018A_Main (R50.1 U1.15)
COMM_SDA: MCU018A_Block (J1.3), MCU018A_Main (R51.1 U1.14)
COMM_TXD: MCU018A_Block (J1.9), MCU018A_Main (U1.17)
D+: MCU018A_Block (USB.3), MCU018A_USB Hub and Pow (R407.1 U400.5)
D-: MCU018A_Block (USB.2), MCU018A_USB Hub and Pow (R409.1 U400.3)
EZFET_SBWTCK_TST: MCU018A_Block (R2.1), MCU018A_ezFET_lite (U100.44 U103.3)
EZFET_SBWTDIO_RST: MCU018A_Block (R1.1), MCU018A_ezFET_lite (U100.43 U103.1)
EZFET_UART_RXD: MCU018A_Block (R4.1), MCU018A_ezFET_lite (U100.38 U103.4)
EZFET_UART_TXD: MCU018A_Block (R3.1), MCU018A_ezFET_lite (U100.37 U103.5)
EZFET_VCCTARGET: MCU018A_Block (J10.1), MCU018A_ezFET_lite (U101.1 U101.5)
HID-BRIDGE_IRQ: MCU018A_Block (R40.1), MCU018A_Comm Interface (R207.1 U200.32 U202.1)
HID-BRIDGE_RXD: MCU018A_Block (R7.1), MCU018A_Comm Interface (U200.38 U201.5)
HID-BRIDGE_SCL: MCU018A_Block (R8.1), MCU018A_Comm Interface (R200.1 U200.35 U202.4)
HID-BRIDGE_SDA: MCU018A_Block (R39.1), MCU018A_Comm Interface (R208.1 U200.34 U202.5)
HID-BRIDGE_TXD: MCU018A_Block (R6.1), MCU018A_Comm Interface (U200.37 U201.4)
HUB_DM1: MCU018A_USB Hub and Pow (R412.2 R414.1), MCU018A_Comm Interface (R201.1)
HUB_DM2: MCU018A_USB Hub and Pow (R405.2 R415.1), MCU018A_ezFET_lite (R101.1)
HUB_DP1: MCU018A_USB Hub and Pow (R411.2 R413.1), MCU018A_Comm Interface (R203.1)
HUB_DP2: MCU018A_USB Hub and Pow (R410.2 R416.1), MCU018A_ezFET_lite (R100.1)
JTAG_RESET: MCU018A_Block (J3.2), MCU018A_Main (5 pins)
JTAG_RXD: MCU018A_Block (J3.6), MCU018A_Main (J34.14 U1.19)
JTAG_TEST: MCU018A_Block (J3.4), MCU018A_Main (J34.8 U1.20)
JTAG_TXD: MCU018A_Block (J3.8), MCU018A_Main (J34.12 U1.18)

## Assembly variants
001: not fitted C9 C15 C16 FID1 FID2 FID3 J100 J200 L3 R20 R21 R22 R26 R41 R42 R43 R44 R45 R46 R47 R48 R49 U2 U3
